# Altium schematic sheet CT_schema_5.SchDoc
size 430 x 429 mm
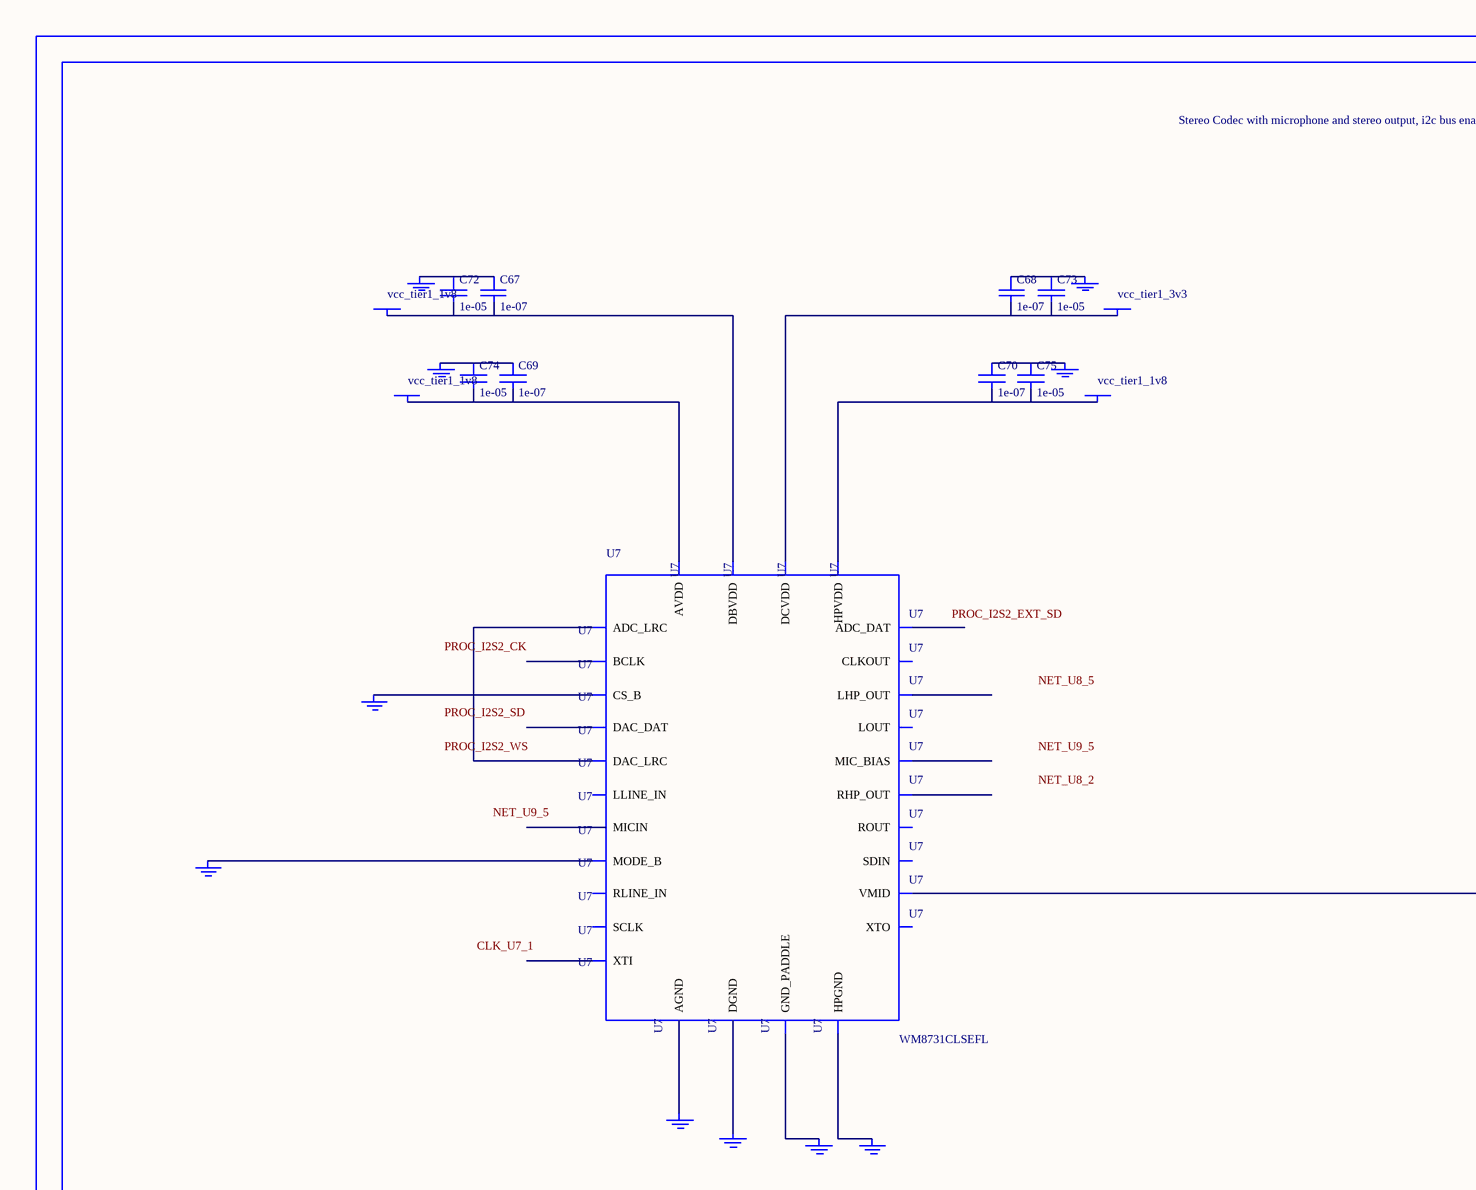
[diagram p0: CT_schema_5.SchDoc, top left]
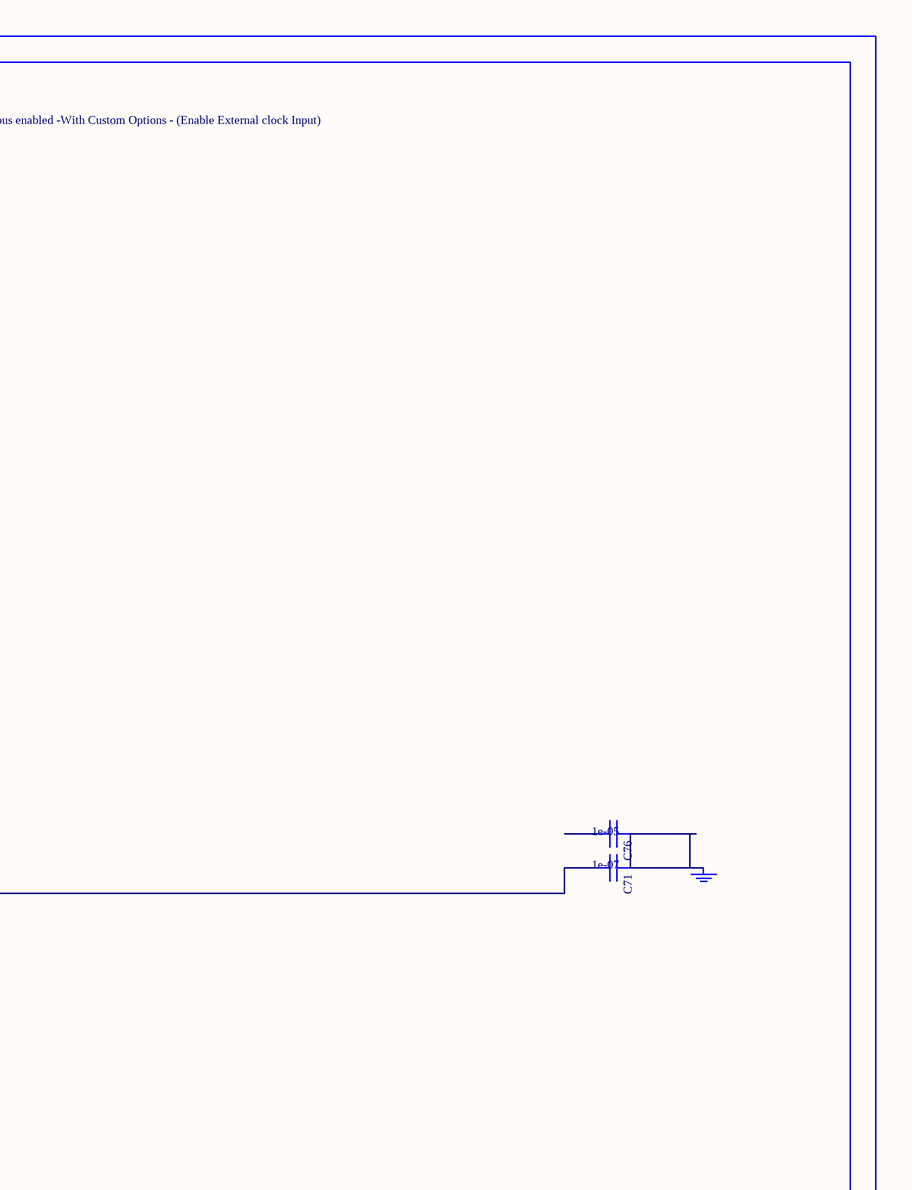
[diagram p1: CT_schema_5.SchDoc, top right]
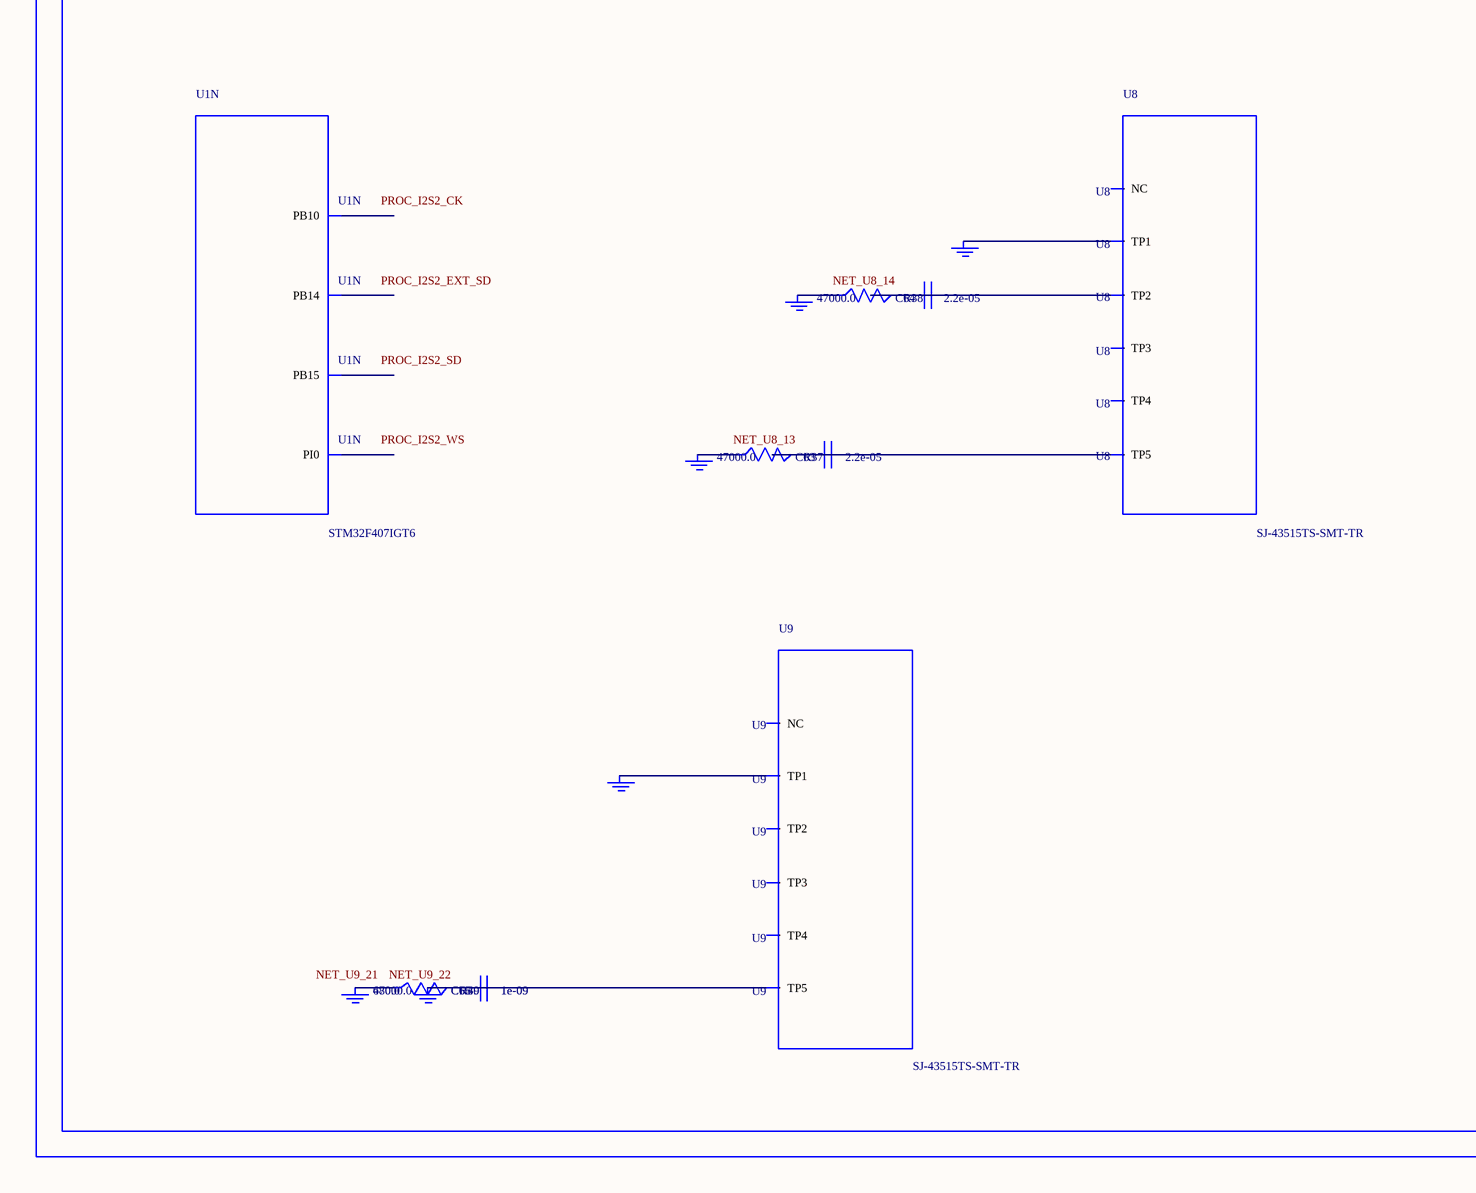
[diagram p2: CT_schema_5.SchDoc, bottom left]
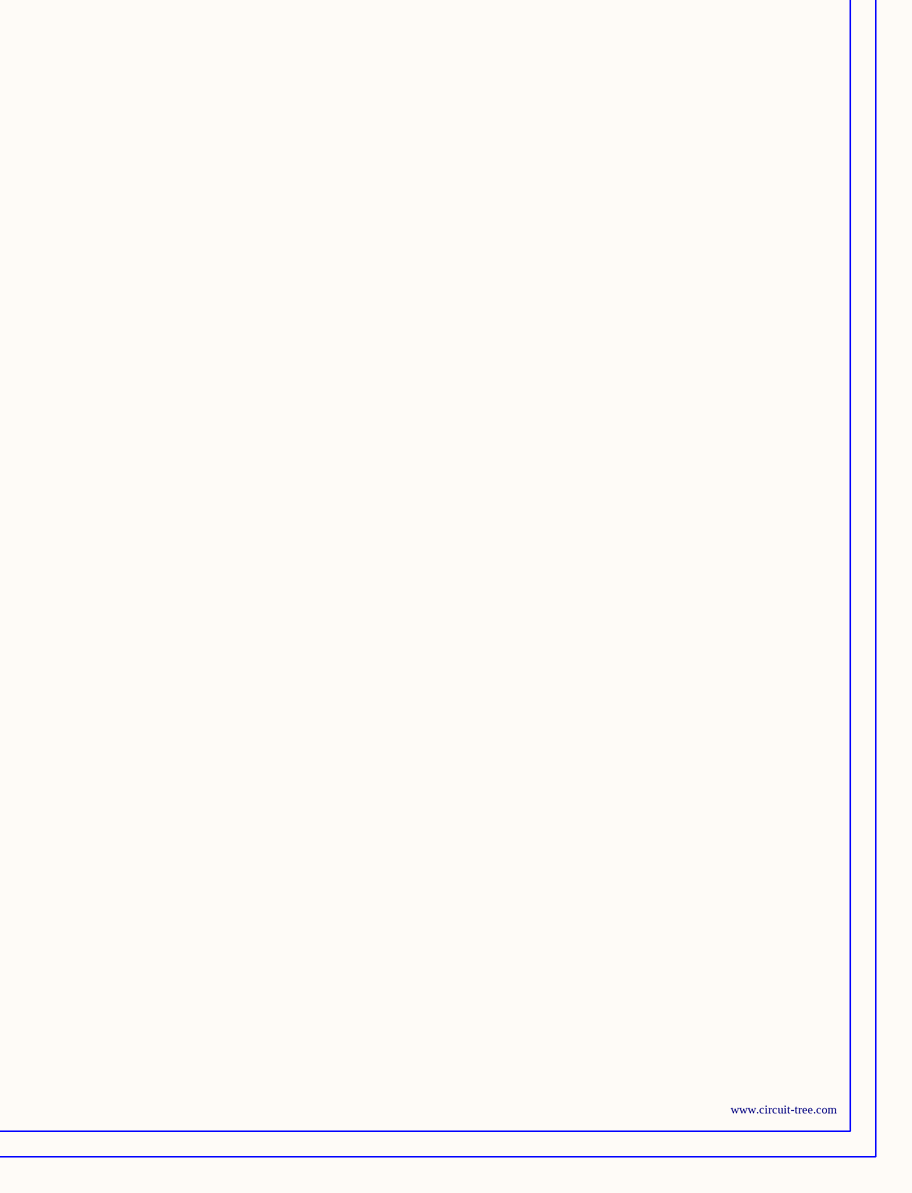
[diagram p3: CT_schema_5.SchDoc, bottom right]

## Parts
BORDER4  (no value)
C63  2.2e-05  [C1210]
C64  2.2e-05  [C1210]
C65  1e-09  [C0402]
C66  1e-09  [C0402]
C67  1e-07  [C0402]
C68  1e-07  [C0402]
C69  1e-07  [C0402]
C70  1e-07  [C0402]
C71  1e-07  [C0402]
C72  1e-05  [C0805]
C73  1e-05  [C0805]
C74  1e-05  [C0805]
C75  1e-05  [C0805]
C76  1e-05  [C0805]
GND_INSTANCE_4_0  (no value)
GND_INSTANCE_4_1  (no value)
GND_INSTANCE_4_2  (no value)
GND_INSTANCE_4_3  (no value)
GND_INSTANCE_4_4  (no value)
GND_INSTANCE_4_5  (no value)
GND_INSTANCE_4_6  (no value)
GND_INSTANCE_4_7  (no value)
GND_INSTANCE_4_8  (no value)
GND_INSTANCE_4_9  (no value)
GND_INSTANCE_4_10  (no value)
GND_INSTANCE_4_11  (no value)
GND_INSTANCE_4_12  (no value)
GND_INSTANCE_4_13  (no value)
GND_INSTANCE_4_14  (no value)
GND_INSTANCE_4_15  (no value)
GND_INSTANCE_4_16  (no value)
POWER_INSTANCE_4_0  vcc_tier1_3v3
POWER_INSTANCE_4_1  vcc_tier1_1v8
POWER_INSTANCE_4_2  vcc_tier1_1v8
POWER_INSTANCE_4_3  vcc_tier1_1v8
R37  47000.0  [R0603]
R38  47000.0  [R0603]
R39  47000.0  [R0603]
R40  680.0  [R0603]
U1  STM32F407IGT6  [LQFP176]  (part N of 14)
U7  WM8731CLSEFL  [QFN-28]
U8  SJ-43515TS-SMT-TR  [SJ-43515TS-SMT-TR]
U9  SJ-43515TS-SMT-TR  [SJ-43515TS-SMT-TR]

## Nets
NetC63_1: C63.1 C63.2 R37.2 U8.5(TP5)
NetC64_1: C64.1 C64.2 R38.2 U8.2(TP2)
NetC65_1: C65.1 C65.2 C66.1 C66.2 GND_INSTANCE_4_16.0(GND) R39.2 R40.2 U9.5(TP5)
NetC67_1: C67.1 C72.1 GND_INSTANCE_4_1.0(GND)
NetC67_2: C67.2 C72.2 POWER_INSTANCE_4_1.0(PWR) U7.5(DBVDD)
NetC68_1: C68.1 C73.1 GND_INSTANCE_4_0.0(GND)
NetC68_2: C68.2 C73.2 POWER_INSTANCE_4_0.0(PWR) U7.3(DCVDD)
NetC69_1: C69.1 C74.1 GND_INSTANCE_4_4.0(GND)
NetC69_2: C69.2 C74.2 POWER_INSTANCE_4_3.0(PWR) U7.18(AVDD)
NetC70_1: C70.1 C75.1 GND_INSTANCE_4_2.0(GND)
NetC70_2: C70.2 C75.2 POWER_INSTANCE_4_2.0(PWR) U7.12(HPVDD)
NetC71_1: C71.1 C76.1 GND_INSTANCE_4_5.0(GND)
NetC71_2: C71.2 U7.20(VMID)
NetGND_INSTANCE_4_3_0: GND_INSTANCE_4_3.0(GND) U7.15(HPGND)
NetGND_INSTANCE_4_6_0: GND_INSTANCE_4_6.0(GND) U7.25(MODE_B)
NetGND_INSTANCE_4_7_0: GND_INSTANCE_4_7.0(GND) U7.26(CS_B)
NetGND_INSTANCE_4_8_0: GND_INSTANCE_4_8.0(GND) U7.29(GND_PADDLE)
NetGND_INSTANCE_4_9_0: GND_INSTANCE_4_9.0(GND) U7.4(DGND)
NetGND_INSTANCE_4_10_0: GND_INSTANCE_4_10.0(GND) U7.19(AGND)
NetGND_INSTANCE_4_11_0: GND_INSTANCE_4_11.0(GND) U8.1(TP1)
NetGND_INSTANCE_4_12_0: GND_INSTANCE_4_12.0(GND) R38.1
NetGND_INSTANCE_4_13_0: GND_INSTANCE_4_13.0(GND) R37.1
NetGND_INSTANCE_4_14_0: GND_INSTANCE_4_14.0(GND) U9.1(TP1)
NetGND_INSTANCE_4_15_0: GND_INSTANCE_4_15.0(GND) R39.1 R40.1
NetU7_9: U7.9(DAC_LRC) U7.11(ADC_LRC)

Not connected (* = marked no-connect by the designer): C76 2; U1 79(PB10) 94(PB14) 95(PB15) 131(PI0); U7 1(XTI) 2(XTO) 6(CLKOUT) 7(BCLK) 8(DAC_DAT) 10(ADC_DAT) 13(LHP_OUT) 14(RHP_OUT) 16(LOUT) 17(ROUT) 21(MIC_BIAS) 22(MICIN) 23(RLINE_IN) 24(LLINE_IN) 27(SDIN) 28(SCLK); U8 3(TP3) 4(TP4) 6(NC); U9 2(TP2) 3(TP3) 4(TP4) 6(NC)

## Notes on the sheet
- Labels drawn without touching a wire or pin: CLK_U7_1, NET_U8_2, NET_U8_5, NET_U8_13, NET_U8_14, NET_U9_5, NET_U9_21, NET_U9_22, PROC_I2S2_CK, PROC_I2S2_EXT_SD, PROC_I2S2_SD, PROC_I2S2_WS

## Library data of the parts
BORDER4 = BORDER_PAGE4
C63 C64 = C1210C224K5RACTU
C65 C66 = C0402C102K3RAC
C67-C71 = C0402C104K3RACTU
C72-C76 = C0805C106K8RACTU
GND_INSTANCE_4_0-GND_INSTANCE_4_16 = GND
POWER_INSTANCE_4_0-POWER_INSTANCE_4_3 = PWR
R37-R39 = RC0603JR-0747KL
R40 = RC0603JR-07680RL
